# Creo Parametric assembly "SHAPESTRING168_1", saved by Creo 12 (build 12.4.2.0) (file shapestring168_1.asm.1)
Units: Custom; MM, KILOGRAM, SECS

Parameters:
  PTC_WM_ITERATION = "0"
  PTC_WM_VERSION = "-.0"
  PTC_WM_LIFECYCLE_STATE = "In Work"
  PTC_WM_LIFECYCLE = "MO_CADDocument"
  PTC_WM_CREATED_BY = "Maximilian Roepper (Z0017RMS: MO)"
  PTC_WM_CREATED_ON = "18-Sep-26 11:36:42 AM"
  PTC_WM_MODIFIED_BY = "Maximilian Roepper (Z0017RMS: MO)"
  PTC_WM_MODIFIED_ON = "18-Sep-26 11:36:46 AM"
  PDMLINKNUMBER = "PDM000071455309"
  PTC_WM_NUMBER = "PDM000071455309"

Other parameters: WEIGHT, WEIGHT_FACTOR, WEIGHT_ADD, MC_ERRORS, SUPPLIER

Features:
  1. coordinate system
  2. imported feature
  3. component "SHAPESTRING080_1"
  4. component "SHAPESTRING166_1"
  5. component "SHAPESTRING167_1"

Other named items: DRW_VIEW_ORG, ROUGH-GROB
